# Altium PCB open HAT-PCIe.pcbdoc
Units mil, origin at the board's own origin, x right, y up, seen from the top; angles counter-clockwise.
Board outline 11336.61 x 3277.39 mil, 2 copper layers (Top Layer, Bottom Layer); 16 components, 20 nets, 86 pads, 116 vias.
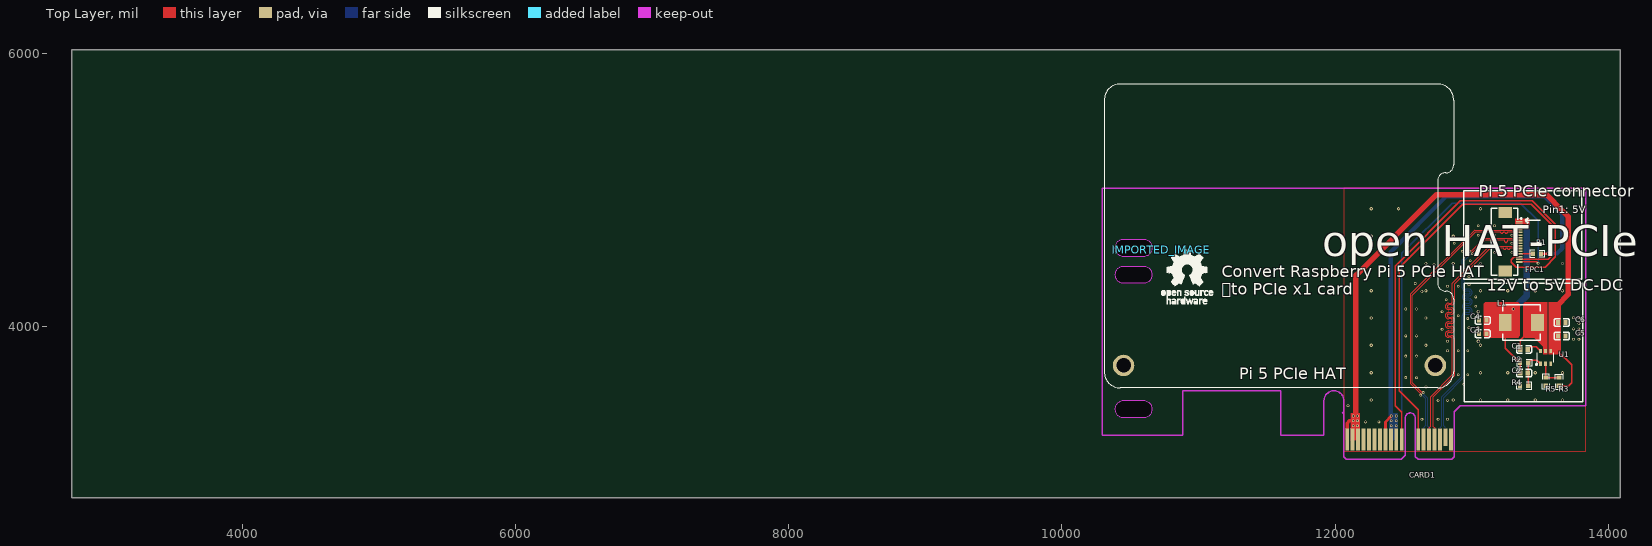
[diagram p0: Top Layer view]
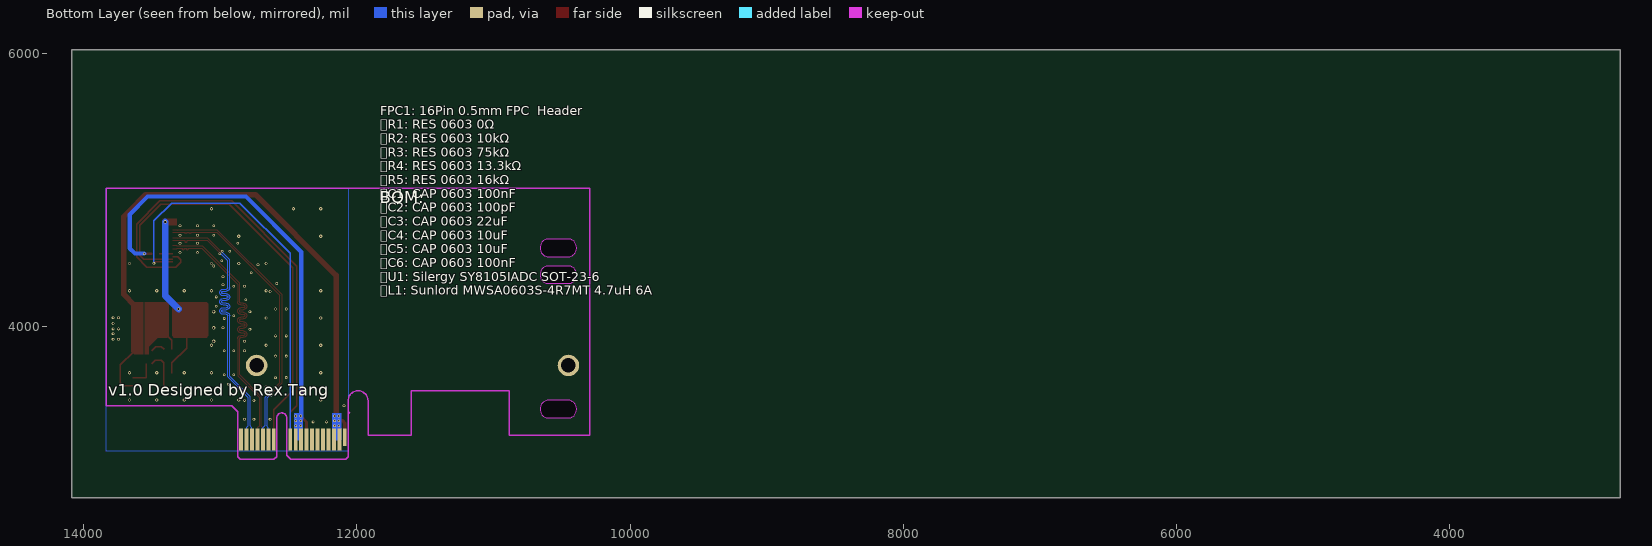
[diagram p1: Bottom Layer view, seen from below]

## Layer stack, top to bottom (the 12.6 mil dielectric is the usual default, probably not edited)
Top Layer: signal copper (thickness not stored)
Dielectric: dielectric 12.6, FR-4, Dk 4.8
Bottom Layer: signal copper (thickness not stored)

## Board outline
14086.61,2750 2750,2750 2750,6027.39 14086.61,6027.39
cut-out: 10450.78,3460.91 10598.42,3460.91 cw(c10598.42,3401.85) 10657.48,3401.85 10657.48,3392.01 cw(c10598.42,3392.01) 10598.42,3332.95 10450.78,3332.95 cw(c10450.78,3392.01) 10391.73,3392.01 10391.73,3401.85 cw(c10450.78,3401.85)
cut-out: 10450.78,4445.16 10598.42,4445.16 cw(c10598.42,4386.1) 10657.48,4386.1 10657.48,4376.26 cw(c10598.42,4376.26) 10598.42,4317.2 10450.78,4317.2 cw(c10450.78,4376.26) 10391.73,4376.26 10391.73,4386.1 cw(c10450.78,4386.1)
cut-out: 10450.78,4642.01 10598.42,4642.01 cw(c10598.42,4582.95) 10657.48,4582.95 10657.48,4573.11 cw(c10598.42,4573.11) 10598.42,4514.06 10450.78,4514.06 cw(c10450.78,4573.11) 10391.73,4573.11 10391.73,4582.95 cw(c10450.78,4582.95)

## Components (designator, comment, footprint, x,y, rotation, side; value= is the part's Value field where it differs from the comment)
C1 "CC0603KRX7R9BB104" C0603 13383.86,3834.92 r0 top
C2 "CC0603JRNPO9BN101" C0603 13383.86,3661.69 r180 top
C3 "CL10A226MQ8NRNC" C0603 13080.71,3949.09 r0 top
C4 "CL10A106KP8NNNC" C0603 13080.71,4047.52 r0 top
C5 "CL10A106KP8NNNC" C0603 13659.45,3933.35 r180 top
C6 "CC0603KRX7R9BB104" C0603 13659.45,4031.77 r180 top
CARD1 "PCIE X1金手指" "PCIE X1金手指" 12143.3,3190 r90 top
FPC1 "FPC-05F-16PH20" FPC-SMD_16P-P0.50_FPC-05F-16PH20 13297.24,4622.32 r270 top
IMPORTED_IMAGE "IMPORTED_IMAGE" IMPORTED_IMAGE 10726.38,4564.84 r0 top
L1 "MWSA0603S-4R7MT" IND-SMD_L7.0-W6.6 13364.17,4031.77 r180 top
R1 "0603WAF0000T5E" R0603 13478.35,4535.71 r180 top
R2 "RC0603FR-07100KL" R0603 13383.86,3736.5 r180 top
R3 "0603WAF7502T5E" R0603 13639.76,3598.7 r270 top
R4 "0603WAF1332T5E" R0603 13383.86,3567.2 r0 top
R5 "0603WAF1602T5E" R0603 13541.34,3598.7 r90 top
U1 "SY8105IADC" TSOT-23-6_L2.9-W1.6-P0.95-LS2.8-BR 13541.34,3775.87 r270 top

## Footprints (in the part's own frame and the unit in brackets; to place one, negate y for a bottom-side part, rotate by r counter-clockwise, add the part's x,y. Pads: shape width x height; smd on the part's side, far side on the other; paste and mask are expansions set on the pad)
C0603 [mm]
  rect 0.8x0.9 smd: 1(-0.7,0) 2(0.7,0)
  silkscreen extent -1.41,-0.71 1.39,0.72
FPC-SMD_16P-P0.50_FPC-05F-16PH20 [mm]
  rect 0.3x1.25 smd: 1(-3.75,1.288) 2(-3.25,1.288) 3(-2.75,1.288) 4(-2.25,1.288) 5(-1.75,1.288) 6(-1.25,1.288) 7(-0.75,1.288) 8(-0.25,1.288) 9(0.25,1.288) 10(0.75,1.288) 11(1.25,1.288) 12(1.75,1.288) 13(2.25,1.288) 14(2.75,1.288) 15(3.25,1.288) 16(3.75,1.288)
  rect 2x2.5 smd: 17(5.44,-1.288) 18(-5.44,-1.288)
  silkscreen extent -6.2,-3.91 6.2,1.78
IMPORTED_IMAGE [mil]
  silkscreen extent 0,-400 381,0
IND-SMD_L7.0-W6.6 [mm]
  rect 2.4x3.2 smd: 1(-3,0) 2(3,0)
  silkscreen extent -3.5,-3.3 3.5,3.3
"PCIE X1金手指" [mil]
  rect 128x28 smd far side: A1(0,55)
  rect 160x28 smd far side: A2(-15,15) A3(-15,-25) A4(-15,-65) A5(-15,-105) A6(-15,-145) A7(-15,-185) A8(-15,-225) A9(-15,-265) A10(-15,-305) A11(-15,-345) A12(-15,-465) A13(-15,-505) A14(-15,-545) A15(-15,-585) A16(-15,-625) A17(-15,-665) A18(-15,-705)
  rect 160x28 smd: B1(-15,55) B2(-14.6,15) B3(-14.6,-25) B4(-14.6,-65) B5(-14.6,-105) B6(-14.6,-145) B7(-14.6,-185) B8(-14.6,-225) B9(-14.6,-265) B10(-14.6,-305) B11(-14.6,-345) B12(-14.6,-465) B13(-14.6,-505) B14(-14.6,-545) B15(-14.6,-585) B16(-14.6,-625) B18(-14.6,-705)
  rect 128x28 smd: B17(1.4,-665)
  Board Outline Layer lines w10: -141,80 174,80 ; -141,80 174,80 ; -141,80 -161,60 ; -141,80 -161,60 ; 174,80 184,90 174,80 ; -161,60 -161,-340 ; -161,60 -161,-340 ; -161,-340 -131,-370 ; -161,-340 -131,-370 ; -131,-370 139,-370 ; -131,-370 139,-370 ; 139,-370 cw(c141.5,-407.5) 139,-445 ; 139,-370 cw(c141.5,-407.5) 139,-445 ; -141,-445 139,-445 ; -141,-445 139,-445 ; -141,-445 -161,-465 ; -141,-445 -161,-465 ; -161,-465 -161,-710 ; -161,-465 -161,-710 ; -161,-710 -141,-730 ; -161,-710 -141,-730 ; -141,-730 179,-730 ; -141,-730 179,-730 ; 179,-730 189,-730 ; 179,-730 189,-730 ; 189,-730 229,-770 189,-730
R0603 [mil]
  rect 31.75x34.02 smd: 1(-29.66,0) 2(29.66,0)
  silkscreen extent -55,-26 55,26
TSOT-23-6_L2.9-W1.6-P0.95-LS2.8-BR [mm]
  rect 0.8x0.532 smd: 1(1.2,-0.95) 2(1.2,0) 3(1.2,0.95) 4(-1.2,0.95) 5(-1.2,0) 6(-1.2,-0.95)
  silkscreen extent -0.88,-1.82 1.44,1.53

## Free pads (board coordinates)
  round 157.48 hole 106.3: 0(10450.78,3716.81) 0(12734.25,3716.81)

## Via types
v1: diameter 19.7, hole 11.8, Top Layer to Bottom Layer, 80 vias
v2: diameter 24, hole 12, Top Layer to Bottom Layer, 31 vias
v3: diameter 25, hole 15, Top Layer to Bottom Layer, 5 vias

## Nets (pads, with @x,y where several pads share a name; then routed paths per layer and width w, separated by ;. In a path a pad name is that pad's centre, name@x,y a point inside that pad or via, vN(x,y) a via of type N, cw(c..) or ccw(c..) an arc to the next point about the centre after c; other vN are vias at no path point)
3.3V: CARD1.A9 CARD1.A10 CARD1.B8 R1.1 | length 3307.1
  Top Layer w20: CARD1.B8 12368.3,3303.62 v1(12411.42,3346.73) ; R1.1 v1(13557.09,4535.71)
  Bottom Layer w30: 12407.48,3327.05 12407.48,4547.52 12812.99,4953.03 13533.46,4953.03 13663.38,4823.11 13663.38,4575.08 13624.01,4535.71 v1(13557.09,4535.71)
  other v1: 12411.42,3275.87 12448.3,3275.6 12411.42,3311.3 12446.85,3311.3 12446.85,3346.73
3.3V_AUX: CARD1.B10
$1N18784: C1.2 U1.6 | length 113.7
  Top Layer w10: C1.2 13431.1,3854.61 13472.44,3854.61 U1.6
$1N18785: C1.1 L1.1 U1.5 | length 117
  Top Layer w10: C1.1 13356.3,3901.85 13391.73,3937.28
$1N18787: C2.1 R2.1 R4.2 U1.1 | length 287.2
  Top Layer w10: R4.2@13413.52,3559.33 R2.1 13433.2,3756.18 13476.38,3756.18 U1.1
$1N18788: R3.1 R5.2 U1.2 | length 198.7
  Top Layer w10: U1.2 R5.2 R3.1
+5V: C2.2 C3.2 C4.2 FPC1.1 FPC1.2 L1.2 R2.2 | length 995.9
  Top Layer w10: 13246.06,3933.35 13246.06,3844.63 R2.2 13356.3,3734.39 C2.2
  Bottom Layer w50: v3(13305.12,4130.2) 13403.54,4228.62 v3(13403.54,4767.99)
+12V: C5.2 C6.2 CARD1.A2 CARD1.A3 CARD1.B1 CARD1.B2 CARD1.B3 R3.2 U1.4 | length 4157.3
  Top Layer w10: 13635.83,3819.17 13734.25,3720.75 13734.25,3590.83 13712.47,3569.04 R3.2
  Top Layer w25: CARD1.B1 12088.3,3295.27 12104.33,3311.3 v1(12131.89,3311.3)
  Top Layer w40: 12151.57,3334.92 12151.57,4375.98 12743.34,4967.74 13546.31,4967.74 13665.93,4848.12 ; 13627.95,4157.76 13706.69,4236.5 13706.69,4807.36 13665.93,4848.12 ; 13683.07,4830.99 13665.93,4848.12
  other v1: 12131.89,3275.87 12163.38,3275.87 12163.38,3311.3 12131.89,3346.73 12163.38,3346.73
GND: C3.1 C4.1 C5.1 C6.1 CARD1.A4 CARD1.A12 CARD1.A15 CARD1.A18 CARD1.B4 CARD1.B7 CARD1.B13 CARD1.B16 CARD1.B18 FPC1.3 FPC1.6 FPC1.9 FPC1.12 R4.1 R5.1 U1.3
  other v1: 12222.44,3303.43 12320.86,3303.43 12635.82,3323.11 12753.93,3323.11 12822.83,3323.11 12094.49,3421.54 12753.93,3460.91 12822.83,3460.91 12665.35,3559.33 12940.94,3579.02 12596.46,3626.26 12517.71,3628.23 12901.57,3647.91 12970.47,3647.91 12517.71,3785.71 12596.45,3785.71 12822.83,3825.08 12901.57,3825.08 12970.47,3825.08 12822.83,3893.98 13746.06,3909.72 13785.43,3909.72 12517.71,3933.35 12596.45,3933.35 13785.43,3949.09 12783.46,3982.56 13746.06,3984.53 13785.43,3984.53 12980.31,3992.4 13785.43,4023.9 12970.47,4061.3 13746.06,4067.21 13785.43,4067.21 12901.57,4080.98 12783.46,4110.51 12517.71,4130.2 12596.45,4130.2 13029.52,4149.88 12812.99,4199.09 13029.52,4218.78 12635.82,4258.15 12822.83,4297.52 12901.57,4297.52 12980.31,4307.36 12586.61,4317.2 12980.31,4366.42 12773.62,4395.94 13049.21,4445.16 12724.41,4455 12990.15,4484.53 13167.32,4543.58 13295.27,4543.58 12931.1,4553.43 12872.04,4612.48 13167.32,4612.48 13295.27,4612.48 13049.21,4671.54 13167.32,4671.54 13295.27,4671.54 13049.21,4740.43 13167.32,4740.43 13295.27,4740.43
  other v2: 12264.96,3464.06 12864.96,3464.06 13064.96,3464.06 13264.96,3464.06 13464.96,3464.06 13664.96,3464.06 12264.96,3664.06 13064.96,3664.06 13264.96,3664.06 13464.96,3664.06 13664.96,3664.06 12264.96,3864.06 12664.96,3864.06 13064.96,3864.06 12264.96,4064.06 12664.96,4064.06 12264.96,4264.06 12664.96,4264.06 13064.96,4264.06 13264.96,4264.06 13464.96,4264.06 13664.96,4264.06 12664.96,4464.06 12864.96,4464.06 13064.96,4464.06 13664.96,4464.06 12264.96,4664.06 12864.96,4664.06 12264.96,4864.06 12464.96,4864.06 13064.96,4864.06
  other v3: 13049.21,3893.98 13049.21,3992.4 13049.21,4110.51
PCIE1_CLK_N: CARD1.A14 FPC1.5 | length 2111.7
  Top Layer w9: v1(12646.44,3518.36) 12638.17,3518.36 12565.7,3590.83 12565.7,4232.5 13027.26,4694.06 13209.17,4694.06 cw(c13209.17,4688.82) 13214.42,4688.82 ccw(c13219.67,4688.82) 13219.67,4683.57 13224.17,4683.57 ccw(c13224.17,4688.81) 13229.42,4688.81 cw(c13234.67,4688.81) 13234.67,4694.06 13239.17,4694.06 cw(c13239.17,4688.82) 13244.42,4688.82 ccw(c13249.67,4688.82) 13249.67,4683.57 13254.17,4683.57 ccw(c13254.17,4688.81) 13259.42,4688.81 cw(c13264.67,4688.81) 13264.67,4694.06 13315.98,4694.06 13318.82,4691.22 FPC1.5
  Bottom Layer w9: v1(12646.44,3518.36) 12646.44,3510.09 12675.3,3481.23 12675.3,3273.68 12688.3,3260.68 CARD1.A14
PCIE1_CLK_P: CARD1.A13 FPC1.4 | length 2110.9
  Top Layer w9: v1(12628.27,3500.19) 12628.27,3508.47 12551.7,3585.03 12551.7,4238.3 13021.47,4708.06 13315.98,4708.06 13318.82,4710.91 FPC1.4
  Bottom Layer w9: v1(12628.27,3500.19) 12636.54,3500.19 12661.3,3475.43 12661.3,3273.75 12648.3,3260.75 CARD1.A13
PCIE1_CLKREQ_N: CARD1.B12 FPC1.15 | length 3161
  Top Layer w10: CARD1.B12 12608.3,3393.94 12470.47,3531.77 12470.47,4433.35 12933.23,4896.1 13436.85,4896.1 13588.58,4744.37 13588.58,4523.9 13559.05,4494.37 FPC1.15
PCIE1_DET_WAKE: CARD1.B11 FPC1.14 | length 3426.7
  Top Layer w10: CARD1.B11 12488.3,3374.29 12438.97,3423.62 12438.97,4445.16 12915.35,4921.54 13442.91,4921.54 13612.2,4752.24 13612.2,4512.09 13537.4,4437.28 13324.8,4437.28 13289.37,4472.72 13289.37,4492.4 13311.02,4514.05 FPC1.14
PCIE1_PWR_EN: FPC1.13 R1.2 | length 101.6
  Top Layer w10: FPC1.13 13446.72,4533.74 R1.2
PCIE1_RST_B: CARD1.A11 FPC1.16 | length 3020.3
  Top Layer w10: FPC1.16 13476.38,4474.68 v1(13486.22,4464.84)
  Bottom Layer w10: CARD1.A11 12488.3,4537.79 12856.3,4905.79 13356.3,4905.79 13486.22,4775.87 v1(13486.22,4464.84)
PCIE1_RX_N: CARD1.A17 FPC1.8 | length 2134.4
  Top Layer w9: v1(13005.18,4535.63) 13005.18,4543.9 13096.29,4635.01 13236.28,4635.01 cw(c13236.28,4627.51) 13243.78,4627.51 13243.78,4624.28 ccw(c13251.28,4624.28) 13258.78,4624.28 13258.78,4627.51 cw(c13266.28,4627.51) 13266.28,4635.01 13315.98,4635.01 13318.82,4632.17 FPC1.8
  Bottom Layer w9: CARD1.A17 12808.3,3262.77 12795.3,3275.77 12795.3,3482.13 12945.91,3632.74 12945.91,4081.6 cw(c12955.91,4081.6) 12955.91,4091.6 12980.36,4091.6 ccw(c12980.36,4115.6) 12980.36,4139.6 12955.91,4139.6 cw(c12955.91,4149.6) 12955.91,4159.6 12980.36,4159.6 ccw(c12980.36,4183.6) 12980.36,4207.6 12955.91,4207.6 cw(c12955.91,4217.6) 12955.91,4227.6 12980.36,4227.6 ccw(c12980.36,4251.6) 12980.36,4275.6 12955.91,4275.6 cw(c12955.91,4285.6) 12945.91,4285.6 12945.91,4484.64 12996.91,4535.63 v1(13005.18,4535.63)
PCIE1_RX_P: CARD1.A16 FPC1.7 | length 2134
  Top Layer w9: v1(12987.01,4553.8) 12995.28,4553.8 13090.49,4649.01 13315.98,4649.01 13318.82,4651.85 FPC1.7
  Bottom Layer w9: CARD1.A16 12768.3,3262.45 12781.3,3275.45 12781.3,3487.93 12931.91,3638.54 12931.91,4081.6 cw(c12955.91,4081.6) 12955.91,4105.6 12980.36,4105.6 ccw(c12980.36,4115.6) 12980.36,4125.6 12955.91,4125.6 cw(c12955.91,4149.6) 12955.91,4173.6 12980.36,4173.6 ccw(c12980.36,4183.6) 12980.36,4193.6 12955.91,4193.6 cw(c12955.91,4217.6) 12955.91,4241.6 12980.36,4241.6 ccw(c12980.36,4251.6) 12980.36,4261.6 12955.91,4261.6 cw(c12955.91,4285.6) 12931.91,4285.6 12931.91,4490.44 12987.01,4545.53 v1(12987.01,4553.8)
PCIE1_TX_N: CARD1.B15 FPC1.11 | length 2114.6
  Top Layer w9: CARD1.B15 12728.3,3259.9 12715.3,3272.9 12715.3,3483.59 12873.28,3641.57 12873.28,3911.76 ccw(c12849.28,3911.76) 12849.28,3935.76 12831.39,3935.76 cw(c12831.39,3945.76) 12831.39,3955.76 12849.28,3955.76 ccw(c12849.28,3979.76) 12849.28,4003.76 12831.39,4003.76 cw(c12831.39,4013.76) 12831.39,4023.76 12849.28,4023.76 ccw(c12849.28,4047.76) 12849.28,4071.76 12831.39,4071.76 cw(c12831.39,4081.76) 12831.39,4091.76 12849.28,4091.76 ccw(c12849.28,4115.76) 12849.28,4139.76 12831.39,4139.76 cw(c12831.39,4149.76) 12831.39,4159.76 12849.28,4159.76 ccw(c12849.28,4183.76) 12873.28,4183.76 12873.28,4313.28 13135.96,4575.95 13229.42,4575.95 cw(c13229.42,4570.95) 13234.43,4570.95 ccw(c13239.43,4570.95) 13239.43,4565.95 13244.42,4565.95 ccw(c13244.42,4570.95) 13249.43,4570.95 cw(c13254.43,4570.95) 13254.43,4575.95 13259.42,4575.95 cw(c13259.42,4570.95) 13264.43,4570.95 ccw(c13269.43,4570.95) 13269.43,4565.95 13274.42,4565.95 ccw(c13274.42,4570.95) 13279.43,4570.95 cw(c13284.43,4570.95) 13284.43,4575.95 13315.98,4575.95 13318.82,4573.11 FPC1.11
PCIE1_TX_P: CARD1.B14 FPC1.10 | length 2114.9
  Top Layer w9: CARD1.B14 12688.3,3259.9 12701.3,3272.9 12701.3,3489.39 12859.28,3647.37 12859.28,3911.76 ccw(c12849.28,3911.76) 12849.28,3921.76 12831.39,3921.76 cw(c12831.39,3945.76) 12831.39,3969.76 12849.28,3969.76 ccw(c12849.28,3979.76) 12849.28,3989.76 12831.39,3989.76 cw(c12831.39,4013.76) 12831.39,4037.76 12849.28,4037.76 ccw(c12849.28,4047.76) 12849.28,4057.76 12831.39,4057.76 cw(c12831.39,4081.76) 12831.39,4105.76 12849.28,4105.76 ccw(c12849.28,4115.76) 12849.28,4125.76 12831.39,4125.76 cw(c12831.39,4149.76) 12831.39,4173.76 12849.28,4173.76 ccw(c12849.28,4183.76) 12859.28,4183.76 12859.28,4319.08 13130.16,4589.95 13315.98,4589.95 13318.82,4592.8 FPC1.10
PRSNT: CARD1.B17
pads on no net: CARD1.A1 CARD1.A5 CARD1.A6 CARD1.A7 CARD1.A8 CARD1.B5 CARD1.B6 CARD1.B9 FPC1.17 FPC1.18

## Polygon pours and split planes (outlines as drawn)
GND on Top Layer (solid, remove dead copper, pour order 0): 12064.96,3086.89 13836.61,3086.89 13836.61,5016.02 12064.96,5016.02
GND on Bottom Layer (solid, remove dead copper, pour order 4): 12064.96,3086.89 13836.61,3086.89 13836.61,5016.02 12064.96,5016.02

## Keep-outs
Board Outline Layer:
  lines w10: 12063.3,3356 12063.3,3384 12063.3,3459.2 ccw(c11990.8,3459.19) 11918.3,3459.19 11918.3,3205 11603.3,3205 11603.3,3530 10883.3,3530 10883.3,3205 10293.3,3205 10293.3,5016.02 13836.61,5016.02 13836.61,3421.54 12911.41,3421.54
Multi-Layer:
  region: 10450.78,3460.91 10598.42,3460.91 cw(c10598.42,3401.85) 10657.48,3401.85 10657.48,3392.01 cw(c10598.42,3392.01) 10598.42,3332.95 10450.78,3332.95 cw(c10450.78,3392.01) 10391.73,3392.01 10391.73,3401.85 cw(c10450.78,3401.85)
  region: 10450.78,4445.16 10598.42,4445.16 cw(c10598.42,4386.1) 10657.48,4386.1 10657.48,4376.26 cw(c10598.42,4376.26) 10598.42,4317.2 10450.78,4317.2 cw(c10450.78,4376.26) 10391.73,4376.26 10391.73,4386.1 cw(c10450.78,4386.1)
  region: 10450.78,4642.01 10598.42,4642.01 cw(c10598.42,4582.95) 10657.48,4582.95 10657.48,4573.11 cw(c10598.42,4573.11) 10598.42,4514.06 10450.78,4514.06 cw(c10450.78,4573.11) 10391.73,4573.11 10391.73,4582.95 cw(c10450.78,4582.95)

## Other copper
Top Layer:
  region net +12V: 12116.14,3169.57 12179.13,3169.57 12179.13,3366.42 12116.14,3366.42
  region net +5V: 13320.86,4744.37 13423.23,4744.37 13423.23,4789.65 13320.86,4789.65
  region net +12V: 13564.96,3799.49 13631.89,3799.49 13651.57,3819.17 13651.57,4181.38 13564.96,4181.38
  region net $1N18785: 13553.15,3799.49 13553.15,4181.38 13387.79,4181.38 13375.98,4169.57 13375.98,3933.35 13387.79,3921.54 13458.66,3921.54 13525.59,3854.61 13525.59,3799.49
  region net +5V: 13340.55,4181.38 13352.36,4169.57 13352.36,3933.35 13340.55,3921.54 13100.19,3921.54 13088.28,3933.45 13088.28,4169.26 13100.39,4181.38
Bottom Layer:
  region net +12V: 12116.14,3169.57 12179.13,3169.57 12179.13,3366.42 12116.14,3366.42
  region net 3.3V: 12395.67,3169.57 12458.66,3169.57 12458.66,3366.42 12395.67,3366.42

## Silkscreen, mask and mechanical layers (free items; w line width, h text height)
Top Silkscreen Layer:
  lines w7.87: 12750.46,3552.98 ccw(c12750.56,3671.09) 12868.67,3671.09 12868.67,4202.59 ; 12750.56,3552.98 10427.72,3552.98 cw(c10427.72,3671.09) 10309.61,3671.09 10309.61,5659.28 cw(c10427.72,5659.28) 10427.72,5777.39 12750.56,5777.39 cw(c12750.56,5659.28) 12868.67,5659.28 12868.67,5186.84 ; 12750.56,4320.7 12750.56,5068.73
  lines w8: 12750.56,4320.7 ccw(c12809.61,4320.7) 12809.61,4261.65 cw(c12809.61,4202.59) 12868.67,4202.59 ; 12750.56,5068.73 cw(c12809.61,5068.73) 12809.61,5127.79 ; 12809.51,5127.79 ccw(c12809.61,5186.84) 12868.67,5186.84
  lines w10: 13413.38,4760.12 13393.7,4779.8 ; 13413.38,4799.49 13393.7,4779.8 ; 13501.97,4779.8 13393.7,4779.8 ; 12941.1,4346.92 13807.24,4346.92 13807.24,4996.53 12941.1,4996.53 12941.1,4346.92 ; 12946.07,3451.06 13812.21,3451.06 13812.21,4317.2 12946.07,4317.2 12946.07,3451.06
  text "PI 5 PCIe connector" at 13052.69,4953.44 h84.96
  text "Pin1: 5V" at 13521.29,4833.22 h56.64
  text "open HAT-PCIe" at 11906.04,4516.82 h226.56
  text "12V to 5V DC-DC" at 13110.9,4264.46 h84.96
  text "Convert Raspberry Pi 5 PCIe HAT /  to PCIe x1 card" at 11169.94,4234.99 h85.78
  text "Pi 5 PCIe HAT" at 11299.45,3614.85 h84.96
Bottom Silkscreen Layer:
  text "BOM:" at 11833.24,4904.54 h89.2
  text "FPC1: 16Pin 0.5mm FPC  Header /  R1: RES 0603 0Ω /  R2: RES 0603 10kΩ /  R3: RES 0603 75kΩ /  R4: RES 0603 13.3kΩ /  R5: RES 0603 16kΩ /  C1: CAP 0603 100nF /  C2: CAP 0603 100pF /  C3: CAP 0603 22uF /  C4: CAP 0603 10uF /  C5: CAP 0603 10uF /  C6: CAP 0603 100nF /  U1: Silergy SY8105IADC SOT-23-6 /  L1: Sunlord MWSA0603S-4R7MT 4.7uH 6A" at 11827.57,4233.63 h67.53
  text "v1.0 Designed by Rex.Tang" at 13821.68,3496.74 h84.96
Top Solder Mask Layer:
  region: 12060.75,3000 12988.3,3000 12988.3,3259.68 12060.75,3259.68
Bottom Solder Mask Layer:
  region: 12060.75,3000 12988.3,3000 12988.3,3259.68 12060.75,3259.68
Mechanical Layer:
  lines w1: 10391.73,3392.01 ccw(c10450.78,3392.01) 10450.78,3332.95 10598.42,3332.95 ccw(c10598.42,3392.01) 10657.48,3392.01 10657.48,3401.85 ccw(c10598.42,3401.85) 10598.42,3460.91 10450.78,3460.91 ccw(c10450.78,3401.85) 10391.73,3401.85 10391.73,3392.01 ; 10391.73,4376.26 ccw(c10450.78,4376.26) 10450.78,4317.2 10598.42,4317.2 ccw(c10598.42,4376.26) 10657.48,4376.26 10657.48,4386.1 ccw(c10598.42,4386.1) 10598.42,4445.16 10450.78,4445.16 ccw(c10450.78,4386.1) 10391.73,4386.1 10391.73,4376.26 ; 10391.73,4573.11 ccw(c10450.78,4573.11) 10450.78,4514.06 10598.42,4514.06 ccw(c10598.42,4573.11) 10657.48,4573.11 10657.48,4582.95 ccw(c10598.42,4582.95) 10598.42,4642.01 10450.78,4642.01 ccw(c10450.78,4582.95) 10391.73,4582.95 10391.73,4573.11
